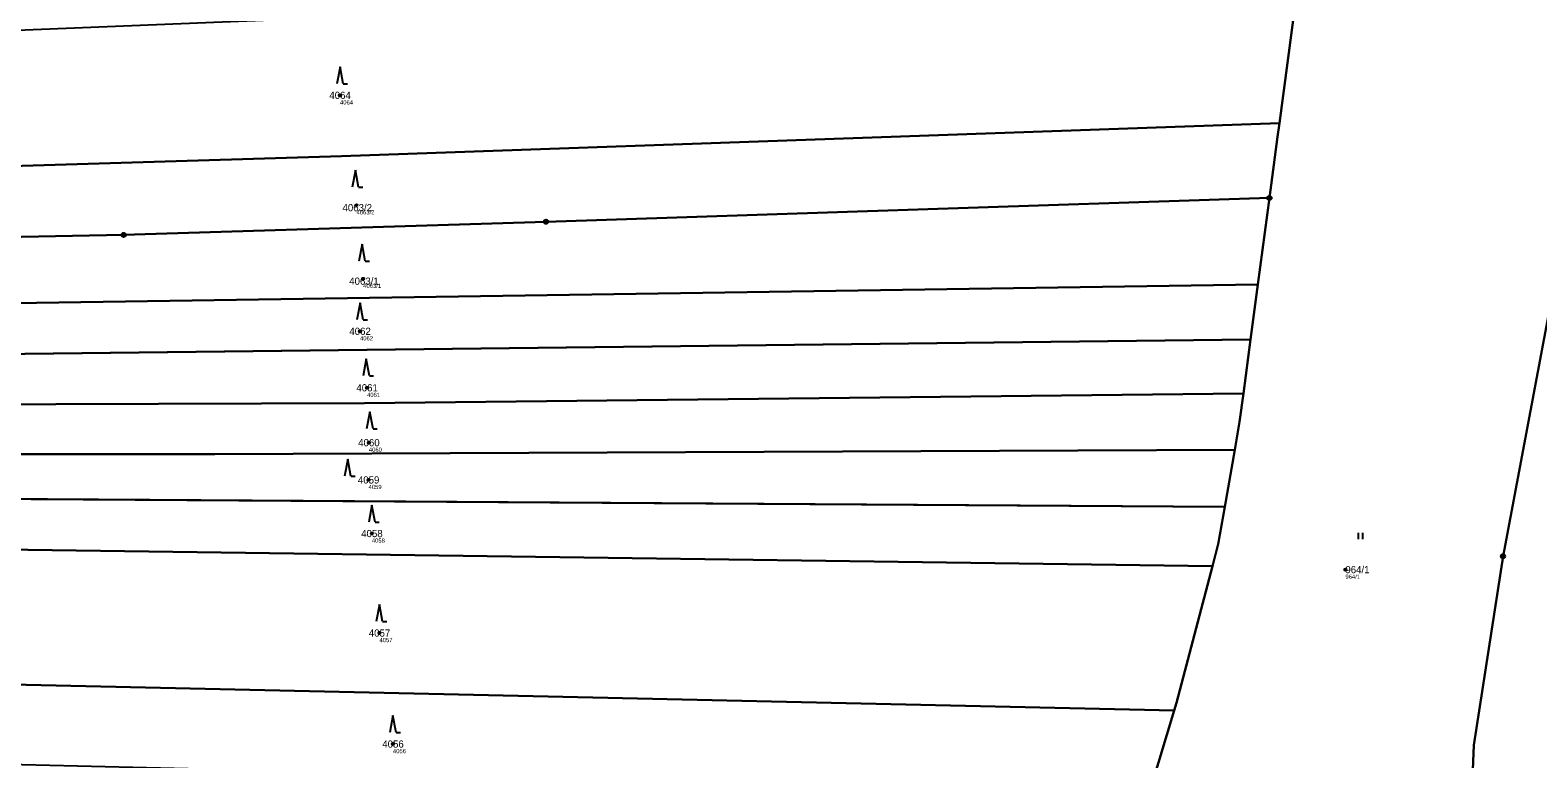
# Model space of a CAD drawing. Extents: x -658203 to -653176, y -1156738 to -1151709.
# Drawn here: x -656749.6 to -656394.6, y -1154244 to -1154072.3 of the extents above; entities that cross this region are included whole.
import ezdxf

# ---------------------------------------------------------------- set-up
doc = ezdxf.new("R2010")
doc.units = 0
for name, color, linetype in [('Vrstva 1', 7, 'Continuous'), ('Vrstva 2', 7, 'Continuous'), ('Vrstva 3', 7, 'Continuous'), ('Vrstva 50', 7, 'Continuous'), ('Vrstva 51', 7, 'Continuous'), ('Vrstva 8', 7, 'Continuous')]:
    doc.layers.add(name, color=color, linetype=linetype)

msp = doc.modelspace()

# ---------------------------------------------------------------- linework, layer by layer
at = {"layer": 'Vrstva 1'}
for p, q in [((-656455.43, -1154094.24), (-656455.86, -1154097.44)), ((-656455.86, -1154097.44), (-656457.78, -1154111.84)), ((-656457.78, -1154111.84), (-656460.5, -1154132.25)), ((-656460.5, -1154132.25), (-656894.63, -1154138.77)), ((-656460.5, -1154132.25), (-656462.22, -1154145.15)), ((-656462.22, -1154145.15), (-656891.8, -1154150.16)), ((-656462.22, -1154145.15), (-656463.91, -1154157.88)), ((-656465.95, -1154171.2), (-656468.28, -1154184.57)), ((-656468.28, -1154184.57), (-656883.9, -1154181.93)), ((-656471.18, -1154198.55), (-656881.17, -1154192.9)), ((-656480.2, -1154232.58), (-656873.5, -1154223.73)), ((-656480.2, -1154232.58), (-656485.6, -1154250.57))]:
    msp.add_line(p, q, dxfattribs=at)
for points in [[(-656450.56, -1154057.63), (-656451.48, -1154064.56), (-656455.43, -1154094.24)], [(-656435.15, -1154343.84), (-656416.66, -1154337.8), (-656412.38, -1154314.64), (-656411.51, -1154286.94), (-656409.68, -1154240.72), (-656402.77, -1154196.23), (-656384.88, -1154101.42), (-656382.24, -1154068.41)], [(-656902.08, -1154108.8), (-656676.28, -1154102.02), (-656455.43, -1154094.24)], [(-656457.78, -1154111.84), (-656628.13, -1154117.43), (-656727.63, -1154120.54), (-656795.85, -1154121.83), (-656898.27, -1154123.81)], [(-656463.91, -1154157.88), (-656670.89, -1154160.16), (-656889.14, -1154160.86)], [(-656463.91, -1154157.88), (-656464.8, -1154164.59), (-656465.95, -1154171.2)], [(-656465.95, -1154171.2), (-656706.15, -1154172.21), (-656886.32, -1154172.18)], [(-656468.28, -1154184.57), (-656469.83, -1154193.42), (-656471.18, -1154198.55)], [(-656471.18, -1154198.55), (-656479.66, -1154230.79), (-656480.2, -1154232.58)]]:
    msp.add_lwpolyline(points, dxfattribs=at)
at = {"layer": 'Vrstva 3'}
for p, q in [((-656676.66, -1154080.96), (-656677.41, -1154084.96)), ((-656675.91, -1154084.96), (-656676.66, -1154080.96)), ((-656675.91, -1154084.96), (-656674.91, -1154084.96)), ((-656673.05, -1154105.26), (-656673.8, -1154109.26)), ((-656672.3, -1154109.26), (-656673.05, -1154105.26)), ((-656672.3, -1154109.26), (-656671.3, -1154109.26)), ((-656671.47, -1154122.71), (-656672.22, -1154126.71)), ((-656670.72, -1154126.71), (-656671.47, -1154122.71)), ((-656670.72, -1154126.71), (-656669.72, -1154126.71)), ((-656671.95, -1154136.54), (-656672.7, -1154140.54)), ((-656671.2, -1154140.54), (-656671.95, -1154136.54)), ((-656671.2, -1154140.54), (-656670.2, -1154140.54)), ((-656670.49, -1154149.73), (-656671.24, -1154153.73)), ((-656669.74, -1154153.73), (-656670.49, -1154149.73)), ((-656669.74, -1154153.73), (-656668.74, -1154153.73)), ((-656669.64, -1154162.18), (-656670.39, -1154166.18)), ((-656668.89, -1154166.18), (-656669.64, -1154162.18)), ((-656668.89, -1154166.18), (-656667.89, -1154166.18)), ((-656674.84, -1154173.4), (-656675.59, -1154177.4)), ((-656674.09, -1154177.4), (-656674.84, -1154173.4)), ((-656674.09, -1154177.4), (-656673.09, -1154177.4)), ((-656669.16, -1154184.18), (-656669.91, -1154188.18)), ((-656668.41, -1154188.18), (-656669.16, -1154184.18)), ((-656668.41, -1154188.18), (-656667.41, -1154188.18)), ((-656436.81, -1154192.2), (-656436.81, -1154190.7)), ((-656435.81, -1154192.2), (-656435.81, -1154190.7)), ((-656667.37, -1154207.61), (-656668.12, -1154211.61)), ((-656666.62, -1154211.61), (-656667.37, -1154207.61)), ((-656666.62, -1154211.61), (-656665.62, -1154211.61)), ((-656664.19, -1154233.76), (-656664.94, -1154237.76)), ((-656663.44, -1154237.76), (-656664.19, -1154233.76)), ((-656663.44, -1154237.76), (-656662.44, -1154237.76))]:
    msp.add_line(p, q, dxfattribs=at)
at = {"layer": 'Vrstva 50'}
for centre in [(-656676.66, -1154087.66), (-656672.76, -1154113.55), (-656671.19, -1154130.86), (-656671.95, -1154143.24), (-656670.29, -1154156.55), (-656669.87, -1154169.47), (-656669.94, -1154178.25), (-656669.16, -1154190.88), (-656439.89, -1154199.38), (-656667.37, -1154214.31), (-656664.19, -1154240.46)]:
    msp.add_circle(centre, 0.25, dxfattribs=at)
at = {"layer": 'Vrstva 51'}
for points in [[(-656382.24, -1154068.41), (-656449.77, -1154051.69), (-656450.56, -1154057.63), (-656451.48, -1154064.56), (-656455.43, -1154094.24), (-656455.86, -1154097.44), (-656457.78, -1154111.84), (-656460.5, -1154132.25), (-656462.22, -1154145.15), (-656463.91, -1154157.88), (-656464.8, -1154164.59), (-656465.95, -1154171.2), (-656468.28, -1154184.57), (-656469.83, -1154193.42), (-656471.18, -1154198.55), (-656479.66, -1154230.79), (-656480.2, -1154232.58), (-656485.6, -1154250.57)], [(-656384.88, -1154101.42), (-656402.77, -1154196.23), (-656409.68, -1154240.72), (-656411.51, -1154286.94), (-656412.38, -1154314.64), (-656416.66, -1154337.8), (-656435.15, -1154343.84), (-656444.11, -1154383.03), (-656453.03, -1154435.64), (-656454.3, -1154445.08), (-656456.89, -1154465.26), (-656457.49, -1154469.91), (-656458.03, -1154474.08), (-656459.84, -1154488.11), (-656459.97, -1154489.1), (-656461.54, -1154502.38), (-656461.99, -1154506.23), (-656393.41, -1154513.49), (-656397.84, -1154566.11), (-656347.42, -1154569.51)], [(-656411.51, -1154286.94), (-656409.68, -1154240.72), (-656402.77, -1154196.23), (-656384.88, -1154101.42)]]:
    msp.add_lwpolyline(points, dxfattribs=at)
for points in [[(-656455.43, -1154094.24), (-656451.48, -1154064.56), (-656450.56, -1154057.63), (-656671.49, -1154069.13), (-656909.54, -1154078.77), (-656902.08, -1154108.8), (-656676.28, -1154102.02)], [(-656455.86, -1154097.44), (-656455.43, -1154094.24), (-656676.28, -1154102.02), (-656902.08, -1154108.8), (-656898.27, -1154123.81), (-656795.85, -1154121.83), (-656727.63, -1154120.54), (-656628.13, -1154117.43), (-656457.78, -1154111.84)], [(-656898.27, -1154123.81), (-656894.63, -1154138.77), (-656460.5, -1154132.25), (-656457.78, -1154111.84), (-656628.13, -1154117.43), (-656727.63, -1154120.54), (-656795.85, -1154121.83)], [(-656460.5, -1154132.25), (-656894.63, -1154138.77), (-656891.8, -1154150.16), (-656462.22, -1154145.15)], [(-656462.22, -1154145.15), (-656891.8, -1154150.16), (-656889.14, -1154160.86), (-656670.89, -1154160.16), (-656463.91, -1154157.88)], [(-656670.89, -1154160.16), (-656889.14, -1154160.86), (-656886.32, -1154172.18), (-656706.15, -1154172.21), (-656465.95, -1154171.2), (-656464.8, -1154164.59), (-656463.91, -1154157.88)], [(-656706.15, -1154172.21), (-656886.32, -1154172.18), (-656883.9, -1154181.93), (-656468.28, -1154184.57), (-656465.95, -1154171.2)], [(-656468.28, -1154184.57), (-656883.9, -1154181.93), (-656881.17, -1154192.9), (-656471.18, -1154198.55), (-656469.83, -1154193.42)], [(-656471.18, -1154198.55), (-656881.17, -1154192.9), (-656873.5, -1154223.73), (-656480.2, -1154232.58), (-656479.66, -1154230.79)], [(-656480.2, -1154232.58), (-656873.5, -1154223.73), (-656868.85, -1154242.42), (-656679.88, -1154247), (-656485.6, -1154250.57)]]:
    msp.add_lwpolyline(points, close=True, dxfattribs=at)
at = {"layer": 'Vrstva 8'}
for centre, radius in [((-656457.78, -1154111.84), 0.5), ((-656457.78, -1154111.84), 0.0303), ((-656628.13, -1154117.43), 0.5), ((-656628.13, -1154117.43), 0.0303), ((-656727.63, -1154120.54), 0.5), ((-656727.63, -1154120.54), 0.0303), ((-656402.77, -1154196.23), 0.5), ((-656402.77, -1154196.23), 0.0303)]:
    msp.add_circle(centre, radius, dxfattribs=at)

# ---------------------------------------------------------------- texts
at = {"layer": 'Vrstva 2'}
for s, p in [('4064', (-656679.17, -1154088.51)), ('4063/2', (-656676.07, -1154114.97)), ('4063/1', (-656674.49, -1154132.28)), ('4062', (-656674.46, -1154144.09)), ('4061', (-656672.8, -1154157.4)), ('4060', (-656672.38, -1154170.32)), ('4059', (-656672.45, -1154179.1)), ('4058', (-656671.67, -1154191.73)), ('964/1', (-656439.89, -1154200.23)), ('4057', (-656669.88, -1154215.16)), ('4056', (-656666.7, -1154241.31))]:
    msp.add_text(s, height=1.7, dxfattribs=at).set_placement(p)
at = {"layer": 'Vrstva 50'}
for s, p in [('4064', (-656676.66, -1154089.82)), ('4063/2', (-656672.76, -1154115.71)), ('4063/1', (-656671.19, -1154133.02)), ('4062', (-656671.95, -1154145.4)), ('4061', (-656670.29, -1154158.71)), ('4060', (-656669.87, -1154171.63)), ('4059', (-656669.94, -1154180.41)), ('4058', (-656669.16, -1154193.04)), ('964/1', (-656439.89, -1154201.54)), ('4057', (-656667.37, -1154216.47)), ('4056', (-656664.19, -1154242.62))]:
    msp.add_text(s, height=1, dxfattribs=at).set_placement(p)

doc.saveas('drawing.dxf')
